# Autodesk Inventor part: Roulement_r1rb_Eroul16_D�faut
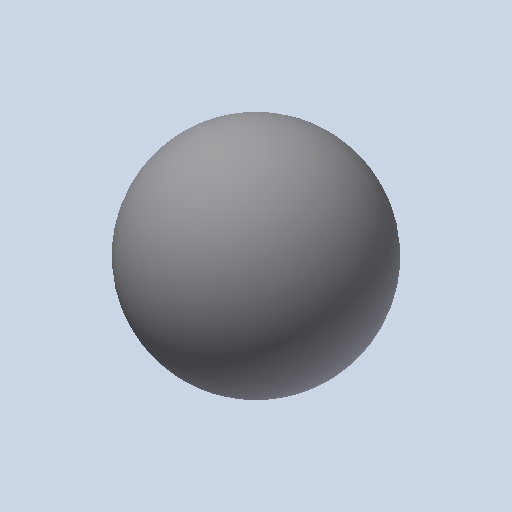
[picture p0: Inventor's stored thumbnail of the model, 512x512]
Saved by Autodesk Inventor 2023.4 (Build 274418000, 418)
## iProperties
Created: 2011-01
Part Number: Roulement_r1rb_Eroul16_D�faut
Document SubType Name: Modeling
Designer: eric
Density: 1 g/cm^3
Mass: 0.0387924 g
Surface Area: 0.554177 cm^2
Volume: 0.0387924 cm^3
Material: Générique
Appearance: Par défaut
Author: eric
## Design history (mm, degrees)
feature "Base1"
node "Corps solides"
node "Corps surfaciques"
node "Solide1"
